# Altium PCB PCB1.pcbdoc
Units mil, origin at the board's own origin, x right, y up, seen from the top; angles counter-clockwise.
Board outline 1155 x 1030 mil, 2 copper layers (Top Layer, Bottom Layer); 7 components, 6 nets, 27 pads, 6 vias.
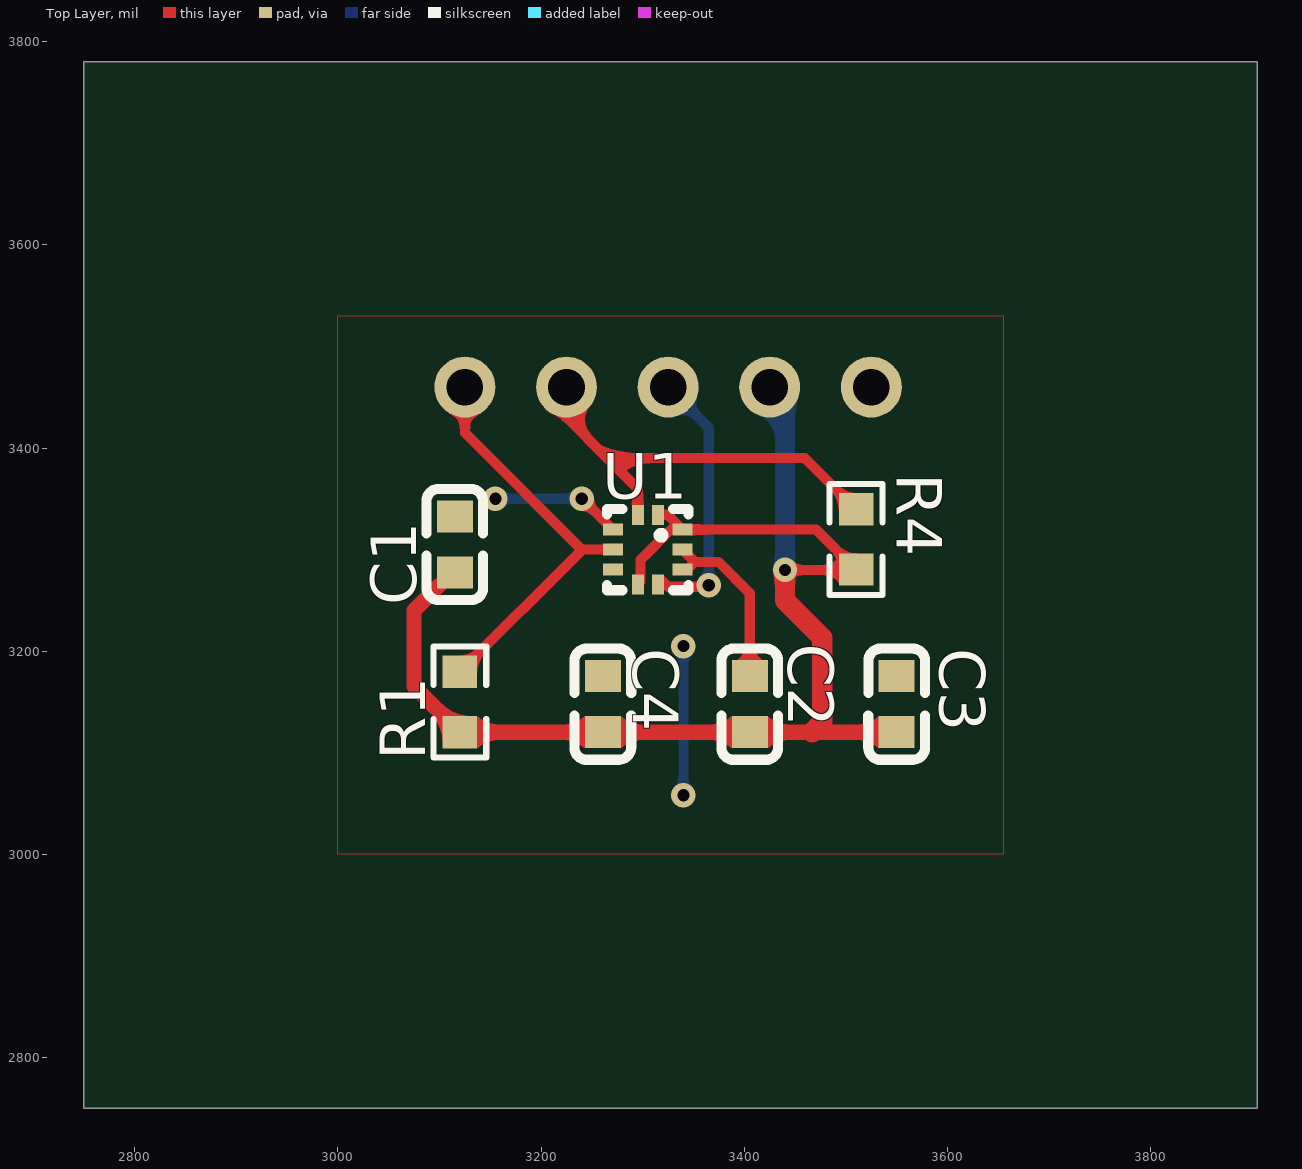
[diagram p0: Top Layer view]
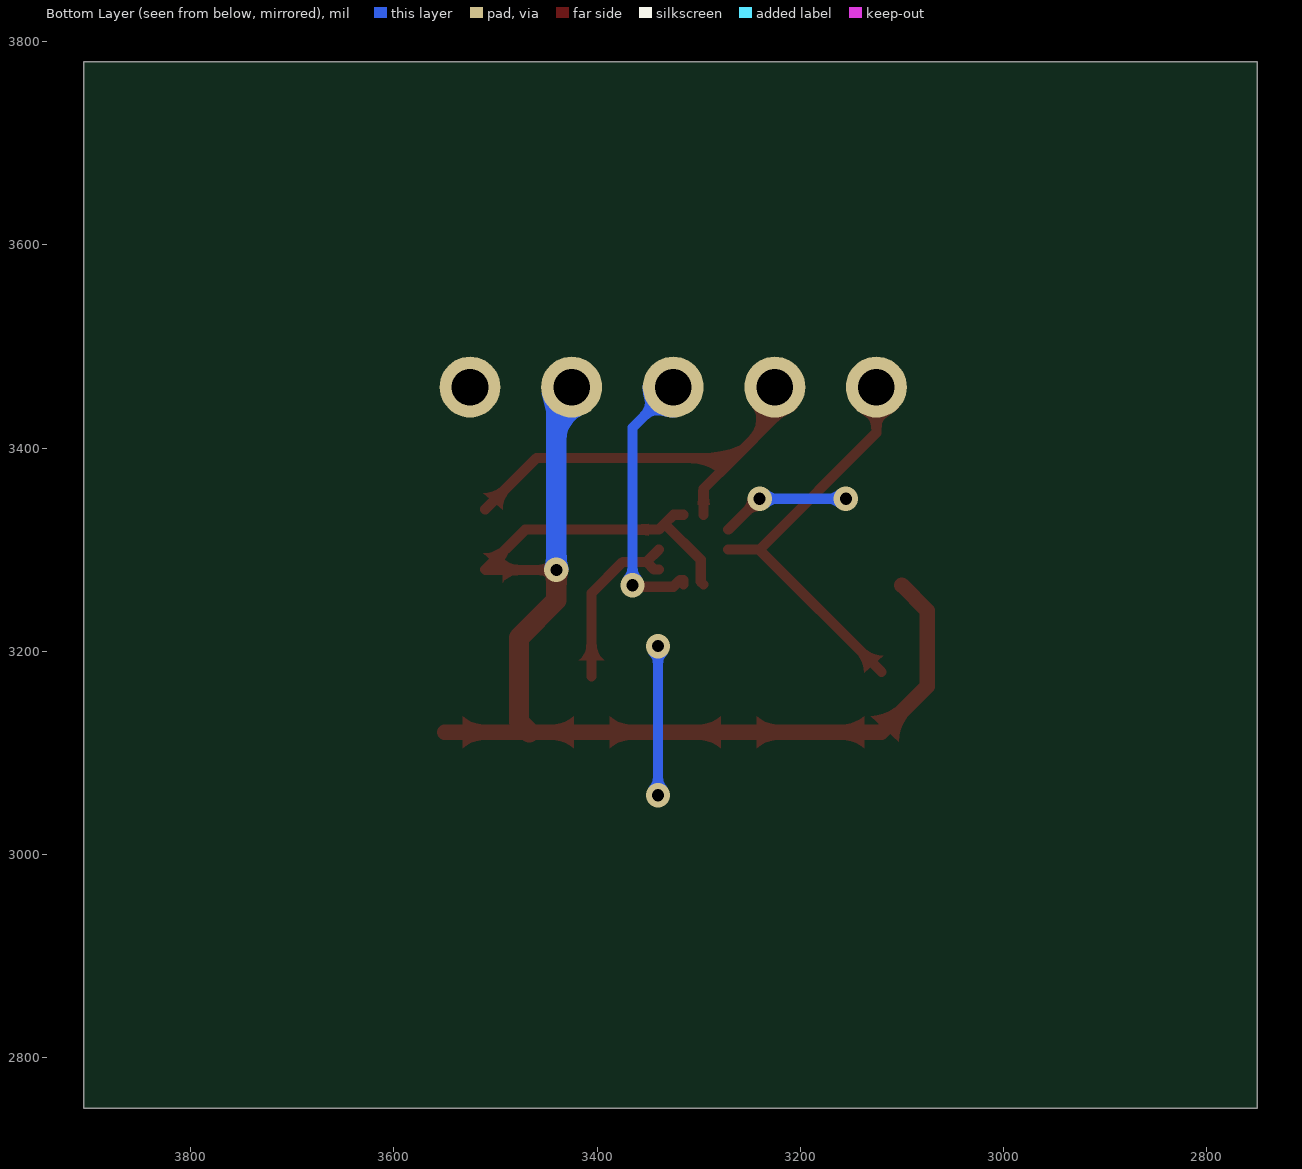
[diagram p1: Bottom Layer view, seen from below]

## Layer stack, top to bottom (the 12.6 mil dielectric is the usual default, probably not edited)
Top Layer: signal copper (thickness not stored)
Dielectric: dielectric 12.6, FR-4, Dk 4.8
Bottom Layer: signal copper (thickness not stored)

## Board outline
3905,2750 2750,2750 2750,3780 3905,3780

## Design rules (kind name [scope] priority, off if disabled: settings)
BoardOutlineClearance copperThickness1oz [All] p0: genericclearance=10 ignorepadtopadclearanceinfootprint=FALSE except(0: Arc-SplitContinuation Track-SplitContinuation SMDPad-SplitContinuation THPad-SplitContinuation Via-SplitContinuation Fill-SplitContinuation Poly-SplitContinuation Region-SplitContinuation Text-SplitContinuation; 6: Track-CutoutEdge SMDPad-CutoutEdge THPad-CutoutEdge Via-CutoutEdge Region-CutoutEdge; 11.8: Track-OutlineEdge SMDPad-OutlineEdge THPad-OutlineEdge Via-OutlineEdge Fill-OutlineEdge Region-OutlineEdge Poly-OutlineEdge Text-OutlineEdge Fill-CutoutEdge)
BoardOutlineClearance copperThickness2oz [All] p0: genericclearance=10 ignorepadtopadclearanceinfootprint=FALSE except(0: Arc-SplitContinuation Track-SplitContinuation SMDPad-SplitContinuation THPad-SplitContinuation Via-SplitContinuation Fill-SplitContinuation Poly-SplitContinuation Region-SplitContinuation Text-SplitContinuation; 6: Track-CutoutEdge SMDPad-CutoutEdge THPad-CutoutEdge Via-CutoutEdge Region-CutoutEdge; 11.8: Track-OutlineEdge SMDPad-OutlineEdge THPad-OutlineEdge Via-OutlineEdge Fill-OutlineEdge Region-OutlineEdge Poly-OutlineEdge Text-OutlineEdge Fill-CutoutEdge)
Clearance copperThickness1oz [(InNet('GND') OR InNet('3.3V') OR InNet('SDA') OR InNet('SCL') OR InNet('INT') OR InNet('SDO'))] p1: gap=7 ignorepadtopadclearanceinfootprint=FALSE except(4: Track-Track; 6: Track-SMDPad SMDPad-SMDPad Track-THPad SMDPad-THPad THPad-THPad Track-Via SMDPad-Via THPad-Via Via-Via SMDPad-Fill THPad-Fill Via-Fill Fill-Fill Track-Region SMDPad-Region THPad-Region Via-Region Region-Region Track-Poly SMDPad-Poly THPad-Poly Via-Poly Fill-Poly Region-Poly Poly-Poly Track-Text SMDPad-Text THPad-Text Via-Text Fill-Text Region-Text Poly-Text Text-Text; 6.9: Track-Hole SMDPad-Hole THPad-Hole Via-Hole Fill-Hole Region-Hole Poly-Hole Text-Hole Sheet-Hole; 11.8: Track-Fill Fill-Region Track-Sheet SMDPad-Sheet THPad-Sheet Via-Sheet Fill-Sheet Region-Sheet Poly-Sheet Text-Sheet)
Clearance copperThickness2oz [All] p1: gap=7 ignorepadtopadclearanceinfootprint=FALSE except(6: Track-SMDPad SMDPad-SMDPad Track-THPad SMDPad-THPad THPad-THPad Track-Via SMDPad-Via THPad-Via Via-Via SMDPad-Fill THPad-Fill Via-Fill Fill-Fill Track-Region SMDPad-Region THPad-Region Via-Region Region-Region Track-Poly SMDPad-Poly THPad-Poly Via-Poly Fill-Poly Region-Poly Poly-Poly Track-Text SMDPad-Text THPad-Text Via-Text Fill-Text Region-Text Poly-Text Text-Text; 6.9: Track-Hole SMDPad-Hole THPad-Hole Via-Hole Fill-Hole Region-Hole Poly-Hole Text-Hole Sheet-Hole; 8: Track-Track; 11.8: Track-Fill Fill-Region Track-Sheet SMDPad-Sheet THPad-Sheet Via-Sheet Fill-Sheet Region-Sheet Poly-Sheet Text-Sheet)
DiffPairsRouting differentialPair [All] p1: maxuncoupledlength=10 minlimit=6 maxlimit=6 mostfreqgap=6 toplayer_minwidth=5 toplayer_prefwidth=10 toplayer_maxwidth=100 bottomlayer_minwidth=5 bottomlayer_prefwidth=10 bottomlayer_maxwidth=100
PasteMaskExpansion pasteMaskExpansion [All] p1: expansion=0
PlaneConnect innerPlane [All] p1: planeconnectstyle=Relief reliefexpansion=20 reliefentries=4 reliefconductorwidth=10 reliefairgap=10
PolygonConnect copperRegion [All] p1: connectstyle=Relief reliefentries=4 reliefconductorwidth=10 polygonreliefangle="90 Angle" airgapwidth=10
RoutingVias viaSize [All] p1: viastyle="Through Hole" holewidth=12.0078 minholewidth=11.811 maxholewidth=248.0314 width=24.0158 minwidth=19.685 maxwidth=393.7008
SolderMaskExpansion solderMaskExpansion [All] p1: useseparateexpansions=TRUE expansion=2 expansionbottom=2
Width copperThickness1oz [All] p1: maxlimit=100 minlimit=5 preferedwidth=10
Width copperThickness2oz [All] p1: maxlimit=100 minlimit=8 preferedwidth=10

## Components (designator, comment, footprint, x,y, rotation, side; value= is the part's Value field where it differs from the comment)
C1 "CAP_0603" C0603 3115,3305 r90 top
C2 "CAP_0603" C0603 3405.35,3147.81 r270 top
C3 "CAP_0603" C0603 3550,3147.81 r90 top
C4 "CAP_0603" C0603 3260.7,3147.81 r90 top
R1 "Res_0603" R0603 3120,3150 r90 top
R4 "Res_0603" R0603 3510,3310 r90 top
U1 "BMP388" SENSORM-SMD_BMP388 3305,3300 r0 top

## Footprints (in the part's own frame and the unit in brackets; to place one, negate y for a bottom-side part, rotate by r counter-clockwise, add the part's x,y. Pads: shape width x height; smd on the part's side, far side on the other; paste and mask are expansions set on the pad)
C0603 [mm]
  rect 0.8x0.9 smd: 1(-0.7,0) 2(0.7,0)
  silkscreen extent -1.39,-0.71 1.39,0.71
R0603 [mil]
  rect 31.75x34.02 smd: 1(-29.66,0) 2(29.66,0)
  silkscreen extent -55,-26 55,26
SENSORM-SMD_BMP388 [mm]
  rect 0.3x0.5 smd: 1(0.25,0.871) 2(-0.25,0.871) 6(-0.25,-0.871) 7(0.25,-0.871)
  rect 0.5x0.3 smd: 3(-0.869,0.5) 4(-0.869,0) 5(-0.869,-0.5) 8(0.869,-0.5) 9(0.869,0) 10(0.869,0.5)
  silkscreen extent -1.02,-1.02 1.02,1.02

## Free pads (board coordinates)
  round 60 hole 36: 1(3125,3460) 1(3225,3460) 1(3325,3460) 1(3525,3460) 2(3425,3460)

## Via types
v1: diameter 24.02, hole 12.01, Top Layer to Bottom Layer, 6 vias

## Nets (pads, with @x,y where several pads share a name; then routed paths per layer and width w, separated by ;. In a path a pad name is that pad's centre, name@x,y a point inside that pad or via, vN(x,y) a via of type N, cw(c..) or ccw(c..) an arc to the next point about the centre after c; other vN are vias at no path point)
3.3V: C1.1 C2.2 C3.1 C4.1 pad.2 R1.1 R4.1 U1.1 U1.6 U1.10 | length 1332.3
  Top Layer w10: U1.6 3297.95,3268.49 3297.95,3290.01 3333.19,3325.26 3333.19,3325.71 ; U1.1 3324.6,3334.3 3333.19,3325.71 ; v1(3440,3280) 3509.66,3280 R4.1 3470.66,3319.68 U1.10 3333.19,3325.71
  Top Layer w15: C1.1@3100,3265 3075,3240 3075,3165.34 R1.1 ; R1.1@3120.09,3120.25 C4.1 C2.2 3466.77,3120.25 C3.1
  Top Layer w20: v1(3440,3280) 3440,3250 3476.77,3213.23 3476.77,3130.25 3466.77,3120.25
  Bottom Layer w20: pad.2 3440,3445 v1(3440,3280)
GND: C1.2 C2.1 C3.2 C4.2 pad.1@3525,3460 U1.3 U1.8 U1.9 | length 309.2
  Top Layer w10: v1(3240,3350) 3240.46,3350 U1.3 ; U1.8 3343.65,3280.31 3351.28,3287.94 ; U1.9 3351.28,3287.94 ; C2.1 3405.35,3257.17 3374.58,3287.94 3351.28,3287.94
  Bottom Layer w10: v1(3155,3350) v1(3240,3350)
INT: pad.1@3325,3460 U1.7 | length 269.3
  Top Layer w10: U1.7 3314.84,3269.85 3318.39,3269.85 3324.83,3263.42 3363.52,3263.42 v1(3365.05,3264.95)
  Bottom Layer w10: pad.1@3325,3460 3365.05,3419.95 v1(3365.05,3264.95)
SCL: pad.1@3225,3460 R4.2 U1.2 | length 420.6
  Top Layer w10: pad.1@3225,3460 3225,3430 3265,3390 ; U1.2 3295.16,3359.84 3265,3390 ; R4.2 3459.66,3390 3265,3390
SDA: pad.1@3125,3460 R1.2 U1.4 | length 408.6
  Top Layer w10: R1.2 3240.34,3300 ; pad.1@3125,3460 3125,3415 3240,3300 3240.34,3300 ; U1.4 3240.34,3300
SDO: U1.5
copper on no net: | length 146.7
  Bottom Layer w10: v1(3340,3058.28) v1(3340,3205)

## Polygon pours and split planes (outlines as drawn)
no net on Top Layer (solid, remove dead copper, pour order 0): 3000,3530 3655,3530 3655,3000 3000,3000

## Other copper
Top Layer:
  region net SCL: 3230,3430 3220,3430 3219.85,3431.15 3219.43,3432.13 3218.76,3432.97 3217.88,3433.68 3216.82,3434.29 3215.62,3434.81 3212.89,3435.7 3209.96,3436.51 3207.08,3437.41 3204.51,3438.57 3203.42,3439.3 3202.5,3440.16 3247.5,3440.16 3246.58,3439.3 3245.49,3438.57 3242.92,3437.41 3240.04,3436.51 3237.11,3435.7 3234.38,3434.81 3233.18,3434.29 3232.12,3433.68 3231.24,3432.97 3230.57,3432.13 3230.15,3431.15
  region net SCL: 3249.57,3412.5 3221.46,3426.46 3218.59,3429.07 3216.1,3430.86 3213.87,3432.12 3211.78,3433.12 3209.72,3434.15 3207.56,3435.48 3205.2,3437.39 3202.5,3440.16 3247.28,3439.92 3246.12,3438.46 3245.16,3436.89 3244.39,3435.22 3243.81,3433.48 3243.41,3431.68 3243.18,3429.84 3243.13,3427.96 3243.24,3426.07 3243.52,3424.19 3243.95,3422.33 3244.54,3420.5 3245.27,3418.73 3246.15,3417.03 3247.16,3415.41 3248.3,3413.9
  region net SDA: 3130,3419.16 3120,3419.16 3119.9,3421.46 3119.61,3423.45 3119.13,3425.16 3118.5,3426.62 3117.7,3427.89 3116.77,3429 3114.53,3430.9 3108.93,3434.55 3105.76,3436.95 3104.14,3438.43 3102.5,3440.16 3147.5,3440.16 3145.86,3438.43 3144.24,3436.95 3141.07,3434.55 3135.47,3430.9 3133.23,3429 3132.3,3427.89 3131.5,3426.62 3130.87,3425.16 3130.39,3423.45 3130.1,3421.46
  region net 3.3V: 3365.13,3112.75 3365.13,3127.75 ccw(c3365.13,3162.56) 3387.63,3136 3387.63,3104.5 ccw(c3365.13,3077.94)
  region net 3.3V: 3445.56,3127.75 3445.56,3112.75 ccw(c3445.56,3077.94) 3423.06,3104.5 3423.06,3136 ccw(c3445.56,3162.56)
  region net GND: 3400.35,3206.12 3410.35,3206.12 ccw(c3429.1,3206.12) 3417.85,3191.12 3392.85,3191.12 ccw(c3381.6,3206.12)
  region net 3.3V: 3509.78,3112.75 3509.78,3127.75 ccw(c3509.78,3162.58) 3532.28,3135.99 3532.28,3104.5 ccw(c3509.78,3077.95)
  region net 3.3V: 3220.49,3112.75 3220.49,3127.75 ccw(c3220.49,3162.56) 3242.99,3135.99 3242.99,3104.5 ccw(c3220.49,3077.93)
  region net 3.3V: 3300.92,3127.75 3300.92,3112.75 ccw(c3300.92,3077.95) 3278.42,3104.5 3278.42,3135.99 ccw(c3300.92,3162.58)
  region net SDA: 3134.11,3200.84 3142.31,3194.9 ccw(c3163.52,3178.99) 3137.01,3178.99 3118.2,3195.54 ccw(c3118.2,3222.05)
  region net 3.3V: 3095.04,3134.7 3106.78,3144.17 ccw(c3130.64,3175.99) 3130.64,3136.22 3102.99,3110.83 ccw(c3063.22,3110.83)
  region net 3.3V: 3159.51,3127.75 3159.51,3112.75 ccw(c3159.51,3078.04) 3137.01,3104.46 3137.01,3136.22 ccw(c3159.51,3161.87)
  region net SCL: 3487.69,3354.9 3495.89,3360.84 ccw(c3511.8,3382.05) 3511.8,3355.54 3492.99,3338.99 ccw(c3466.48,3338.99)
  region net 3.3V: 3477.99,3275 3477.99,3285 ccw(c3477.99,3303.75) 3492.99,3292.5 3492.99,3267.5 ccw(c3477.99,3256.25)
  region net 3.3V: 3487.69,3295.58 3495.89,3301.52 ccw(c3511.8,3322.73) 3511.8,3296.22 3492.99,3279.67 ccw(c3466.48,3279.67)
  region net 3.3V: 3364.06,3324.68 3364.06,3314.68 ccw(c3364.06,3189.99) 3349.06,3313.77 3349.06,3325.59 ccw(c3364.06,3449.37)
  region net SCL: 3290.16,3359.14 3300.16,3359.14 ccw(c3424.85,3359.14) 3301.07,3344.14 3289.25,3344.14 ccw(c3165.47,3359.14)
  region net 3.3V: 3450,3265.59 3430,3265.59 3429.91,3268.24 3429.69,3270.74 3429,3275.12 3428.31,3278.34 3427.99,3280 3452.01,3280 3451.69,3278.34 3451,3275.12 3450.31,3270.74 3450.09,3268.24
  region net 3.3V: 3456.35,3285 3456.35,3275 3455.21,3274.91 3454.08,3274.66 3451.86,3273.75 3449.79,3272.47 3447.94,3270.99 3447.94,3289.01 3449.79,3287.53 3451.86,3286.25 3454.08,3285.34 3455.21,3285.09
  region net GND: 3255.15,3342.38 3248.42,3334.96 3247.56,3335.7 3246.57,3336.32 3244.33,3337.24 3241.93,3337.78 3239.57,3338 3251.96,3351.08 3252.27,3348.74 3252.85,3346.4 3253.78,3344.22 3254.41,3343.25
  region net SCL: 3297.07,3395 cw(c3297.07,3495.71) 3260,3402.07 3265,3390 3284.14,3377.93 cw(c3307.07,3344.29) 3307.07,3385
Bottom Layer:
  region net 3.3V: 3450,3433.07 3430,3410.57 3429.92,3412.1 3429.69,3413.67 3428.8,3416.88 3427.4,3420.07 3425.58,3423.12 3423.4,3425.92 3420.93,3428.33 3418.25,3430.26 3416.86,3430.99 3415.44,3431.57 3454.41,3454.07 3453.25,3449.26 3451.79,3443.61 3450.53,3437.93 3450.14,3435.34
  region net INT: 3357.42,3434.66 3350.34,3427.58 3348.64,3429.14 3347.03,3430.34 3345.49,3431.22 3344,3431.8 3342.55,3432.14 3341.1,3432.26 3338.18,3432.02 3331.63,3430.64 3327.7,3430.1 3325.5,3430 3323.12,3430.06 3354.94,3461.88 3355,3459.5 3354.9,3457.3 3354.36,3453.37 3352.98,3446.82 3352.74,3443.9 3352.86,3442.45 3353.2,3441 3353.78,3439.51 3354.66,3437.97 3355.86,3436.36
  region net INT: 3360.05,3281.3 3370.05,3281.3 3370.14,3280.16 3370.4,3279.03 3371.3,3276.81 3372.59,3274.74 3374.06,3272.89 3356.05,3272.89 3357.52,3274.74 3358.8,3276.81 3359.71,3279.03 3359.96,3280.16
  region net 3.3V: 3430,3294.41 3450,3294.41 3450.09,3291.76 3450.31,3289.26 3451,3284.88 3451.69,3281.66 3452.01,3280 3427.99,3280 3428.31,3281.66 3429,3284.88 3429.69,3289.26 3429.91,3291.76
  region: 3345,3188.65 3335,3188.65 3334.91,3189.79 3334.66,3190.92 3333.75,3193.14 3332.47,3195.21 3330.99,3197.06 3349.01,3197.06 3347.53,3195.21 3346.25,3193.14 3345.34,3190.92 3345.09,3189.79
  region: 3335,3074.63 3345,3074.63 3345.09,3073.49 3345.34,3072.35 3346.25,3070.14 3347.53,3068.07 3349.01,3066.22 3330.99,3066.22 3332.47,3068.07 3333.75,3070.14 3334.66,3072.35 3334.91,3073.49
  region net GND: 3223.65,3345 3223.65,3355 3224.79,3355.09 3225.92,3355.34 3228.14,3356.25 3230.21,3357.53 3232.06,3359.01 3232.06,3340.99 3230.21,3342.47 3228.14,3343.75 3225.92,3344.66 3224.79,3344.91
  region net GND: 3171.35,3355 3171.35,3345 3170.21,3344.91 3169.08,3344.66 3166.86,3343.75 3164.79,3342.47 3162.94,3340.99 3162.94,3359.01 3164.79,3357.53 3166.86,3356.25 3169.08,3355.34 3170.21,3355.09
